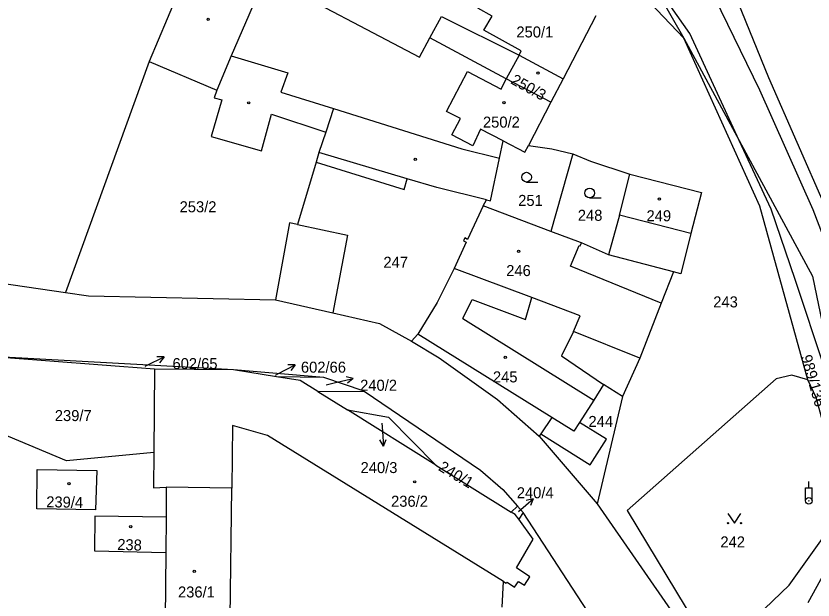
# Model space of a CAD drawing. Extents: x -757266 to -753360, y -1162585 to -1157740.
# Drawn here: x -755076.1 to -754953.1, y -1161480 to -1161389.8 of the extents above; entities that cross this region are included whole.
import ezdxf

# ---------------------------------------------------------------- set-up
doc = ezdxf.new("R2010")
doc.units = 0
for name, color, linetype in [('Hranice parcel', 7, 'Continuous'), ('Parcelní čísla', 7, 'Continuous'), ('Pop  PČ popisy', 7, 'Continuous'), ('Poz předměty', 7, 'Continuous'), ('Vnitřní kresba', 7, 'Continuous'), ('Značky budov', 7, 'Continuous'), ('Značky kultur', 7, 'Continuous')]:
    doc.layers.add(name, color=color, linetype=linetype)

msp = doc.modelspace()

# ---------------------------------------------------------------- linework, layer by layer
at = {"layer": 'Hranice parcel'}
for p, q in [((-755048.2, -1161379.47), (-755055.56, -1161396.89)), ((-754979.4, -1161382.11), (-754973.01, -1161393.26)), ((-754986.59, -1161389.82), (-754991.63, -1161399.56)), ((-755055.56, -1161396.89), (-755068.43, -1161432.57)), ((-754991.63, -1161399.56), (-754993.55, -1161403.18)), ((-754993.55, -1161403.18), (-754997, -1161409.84)), ((-754990.14, -1161411.15), (-754993.55, -1161423.12)), ((-754982.98, -1161420.63), (-754981.34, -1161414.29)), ((-755004.02, -1161419.18), (-755003.49, -1161418.25)), ((-754993.55, -1161423.12), (-755004.02, -1161419.18)), ((-754971.94, -1161423.45), (-754982.98, -1161420.63)), ((-755042.52, -1161444.48), (-755081.11, -1161442.37)), ((-755054.7, -1161444.4), (-755081.11, -1161442.37)), ((-754979.84, -1161442.68), (-754982.48, -1161448.61)), ((-755054.7, -1161444.4), (-755054.84, -1161457.25)), ((-755042.52, -1161444.48), (-755054.7, -1161444.4)), ((-755028.6, -1161445.65), (-755042.52, -1161444.48)), ((-755035.91, -1161445.56), (-755042.52, -1161444.48)), ((-755028.6, -1161445.65), (-755035.91, -1161445.56)), ((-755022.34, -1161447.76), (-755028.6, -1161445.65)), ((-755029.52, -1161447.84), (-755022.34, -1161447.76)), ((-755029.52, -1161447.84), (-755024.95, -1161450.69)), ((-754982.48, -1161448.61), (-754986.4, -1161465.19)), ((-755011.3, -1161459.19), (-755024.95, -1161450.69)), ((-754995.37, -1161454.74), (-754986.4, -1161465.19)), ((-755011.3, -1161459.19), (-754999.67, -1161466.44)), ((-755052.93, -1161462.61), (-755052.94, -1161467.24)), ((-754998.72, -1161465.52), (-754999.67, -1161466.44)), ((-754997.85, -1161466.5), (-754998.72, -1161465.52)), ((-754986.4, -1161465.19), (-754969.21, -1161489.94)), ((-755052.94, -1161467.24), (-755052.95, -1161472.69)), ((-754997.85, -1161466.5), (-754998.51, -1161467.56)), ((-754978.62, -1161495.89), (-754997.85, -1161466.5)), ((-755052.95, -1161472.69), (-755053.17, -1161489.72)), ((-755001.04, -1161481.14), (-755000.88, -1161477.19))]:
    msp.add_line(p, q, dxfattribs=at)
for points in [[(-754973.01, -1161393.26), (-754992.87, -1161372.36), (-755014.97, -1161353.78), (-755031.64, -1161333.48)], [(-755013.14, -1161343.79), (-754982.7, -1161367.02), (-754964.72, -1161387.71), (-754959.99, -1161399.35), (-754951.21, -1161419.33), (-754946.51, -1161428.67)], [(-755048.2, -1161379.47), (-755037.56, -1161383.7), (-755013.83, -1161396.2), (-755012.21, -1161393.22)], [(-755012.21, -1161393.22), (-755010.42, -1161389.94), (-754998.45, -1161395.88), (-754991.63, -1161399.56)], [(-754993.55, -1161403.18), (-755000.43, -1161399.58), (-755012.21, -1161393.22)], [(-754953.91, -1161446.03), (-754961.29, -1161419.21), (-754973.01, -1161393.26)], [(-754973.01, -1161393.26), (-754964.47, -1161409.1), (-754953.18, -1161430.02), (-754949.55, -1161447.4), (-754946.29, -1161464.12)], [(-755191.52, -1161394.71), (-755190.39, -1161394.84), (-755136.4, -1161414.19), (-755092.74, -1161429.01), (-755068.43, -1161432.57)], [(-755055.56, -1161396.89), (-755045.08, -1161401.31), (-755045.52, -1161402.47), (-755044.33, -1161402.81), (-755045.95, -1161408.44), (-755038.18, -1161410.68), (-755036.65, -1161405.03), (-755028.27, -1161407.81), (-755029.34, -1161410.94)], [(-755003.49, -1161418.25), (-755002.86, -1161418.4), (-755001.48, -1161411.8), (-755000.92, -1161409.13), (-754997.56, -1161410.87), (-754997, -1161409.84)], [(-754997, -1161409.84), (-754993.42, -1161410.38), (-754990.14, -1161411.15)], [(-755029.34, -1161410.94), (-755029.78, -1161412.42), (-755032.63, -1161422.04), (-755033.86, -1161421.77), (-755036.04, -1161433.7)], [(-755003.49, -1161418.25), (-755011.15, -1161416.35), (-755015.73, -1161414.99), (-755029.34, -1161410.94)], [(-754990.14, -1161411.15), (-754987.45, -1161412.29), (-754981.34, -1161414.29)], [(-754981.34, -1161414.29), (-754970.29, -1161417.11), (-754971.94, -1161423.45)], [(-755004.02, -1161419.18), (-755006.39, -1161424.34), (-755006.84, -1161424.13), (-755007.05, -1161424.57), (-755006.6, -1161424.78), (-755008.46, -1161428.84)], [(-754982.98, -1161420.63), (-754984.68, -1161426.71), (-754988.81, -1161424.9), (-754989, -1161424.83), (-754993.55, -1161423.12)], [(-754971.94, -1161423.45), (-754973.49, -1161429.65), (-754974.61, -1161429.35), (-754976.53, -1161434.21), (-754979.84, -1161442.68)], [(-755008.46, -1161428.84), (-755011.08, -1161434.1), (-755014.1, -1161438.97), (-755015.04, -1161440.07)], [(-754979.84, -1161442.68), (-754990.07, -1161438.58), (-754989.02, -1161436.13), (-754996.47, -1161433.34), (-755008.46, -1161428.84)], [(-755068.43, -1161432.57), (-755064.89, -1161433.06), (-755036.04, -1161433.7)], [(-755036.04, -1161433.7), (-755027.2, -1161435.69), (-755020.01, -1161437.34), (-755015.04, -1161440.07)], [(-755015.04, -1161440.07), (-755010.8, -1161442.63), (-755001.79, -1161449.07), (-754995.37, -1161454.74)], [(-755029.52, -1161447.84), (-755032.24, -1161446.16), (-755035.91, -1161445.56)], [(-754953.91, -1161446.03), (-754956.35, -1161445.32), (-754958.79, -1161445.88), (-754981.78, -1161466.23), (-754968.18, -1161488.69)], [(-754951.1, -1161469.8), (-754949.73, -1161466.39), (-754949.35, -1161463.05), (-754949.71, -1161459.34), (-754952.59, -1161448.77), (-754953.91, -1161446.03)], [(-754982.48, -1161448.61), (-754985.43, -1161446.75), (-754986.91, -1161449.16), (-754989.15, -1161452.64), (-754990, -1161453.97), (-754993.42, -1161451.84), (-754995.09, -1161454.35), (-754995.37, -1161454.74)], [(-755022.34, -1161447.76), (-755004.4, -1161459.96), (-755000.98, -1161462.96), (-754998.72, -1161465.52)], [(-755024.95, -1161450.69), (-755018.59, -1161451.8), (-755011.3, -1161459.19)], [(-755054.84, -1161457.25), (-755068.32, -1161458.53), (-755084.64, -1161451.67)], [(-755000.88, -1161477.19), (-755037.27, -1161454.63), (-755040.14, -1161453.82), (-755042.68, -1161453.1), (-755042.78, -1161462.74), (-755052.93, -1161462.61)], [(-755054.84, -1161457.25), (-755054.89, -1161462.7), (-755052.93, -1161462.61)], [(-755072.86, -1161465.97), (-755072.8, -1161459.87), (-755063.61, -1161460.04), (-755063.8, -1161466.1), (-755072.86, -1161465.97)], [(-755052.94, -1161467.24), (-755063.93, -1161467.1), (-755064, -1161472.46), (-755052.95, -1161472.69)], [(-754998.51, -1161467.56), (-754999.04, -1161466.83), (-754999.67, -1161466.44)], [(-755000.88, -1161477.19), (-755000.46, -1161477.45), (-755000.31, -1161477.27), (-754999.14, -1161478.03), (-754998.57, -1161477.18), (-754997.64, -1161477.75), (-754996.81, -1161476.46), (-754998.87, -1161475.05), (-754996.29, -1161470.65), (-754998.51, -1161467.56)], [(-754968.18, -1161488.69), (-754956.77, -1161477.72), (-754951.1, -1161469.8)]]:
    msp.add_lwpolyline(points, dxfattribs=at)
at = {"layer": 'Pop  PČ popisy'}
for p, q in [((-755055.94, -1161443.81), (-755053.243, -1161442.494)), ((-755053.243, -1161442.494), (-755054.362, -1161442.483)), ((-755053.243, -1161442.494), (-755053.923, -1161443.384)), ((-755056.17, -1161443.93), (-755055.94, -1161443.81)), ((-755035.66, -1161445.1), (-755033.01, -1161443.691)), ((-755033.01, -1161443.691), (-755034.13, -1161443.719)), ((-755033.01, -1161443.691), (-755033.659, -1161444.603)), ((-755036.02, -1161445.3), (-755035.66, -1161445.1)), ((-755026.97, -1161446.52), (-755024.046, -1161445.845)), ((-755024.046, -1161445.845), (-755025.134, -1161445.582)), ((-755024.046, -1161445.845), (-755024.909, -1161446.558)), ((-755028.25, -1161446.82), (-755026.97, -1161446.52)), ((-755019.62, -1161452.74), (-755019.58, -1161453.29)), ((-755019.58, -1161453.29), (-755019.371, -1161456.284)), ((-755019.371, -1161456.284), (-755019.94, -1161455.32)), ((-755019.371, -1161456.284), (-755018.941, -1161455.25)), ((-754998.54, -1161466.35), (-754996.275, -1161464.381)), ((-754996.275, -1161464.381), (-754997.359, -1161464.66)), ((-754996.275, -1161464.381), (-754996.702, -1161465.416)), ((-754998.57, -1161466.38), (-754998.54, -1161466.35))]:
    msp.add_line(p, q, dxfattribs=at)
at = {"layer": 'Poz předměty'}
for p, q in [((-754953.75, -1161462.716), (-754953.75, -1161461.716)), ((-754954.25, -1161462.716), (-754953.25, -1161462.716)), ((-754954.25, -1161464.716), (-754954.25, -1161462.716)), ((-754953.25, -1161464.716), (-754953.25, -1161462.716))]:
    msp.add_line(p, q, dxfattribs=at)
for radius in [0.5, 0.0303]:
    msp.add_circle((-754953.75, -1161464.7176), radius, dxfattribs=at)
at = {"layer": 'Vnitřní kresba'}
for p, q in [((-754972.12, -1161392.56), (-754979.4, -1161382.11)), ((-755037.56, -1161383.7), (-755042.86, -1161395.99)), ((-754969.29, -1161384.92), (-754961.36, -1161401.24)), ((-755002.62, -1161389.87), (-755004.8, -1161388.66)), ((-755003.92, -1161392.06), (-755002.62, -1161389.87)), ((-754998.12, -1161395.22), (-755003.92, -1161392.06)), ((-754964.47, -1161409.1), (-754972.12, -1161392.56)), ((-754998.45, -1161395.88), (-755000.43, -1161399.58)), ((-754998.45, -1161395.88), (-754998.12, -1161395.22)), ((-755042.86, -1161395.99), (-755045.08, -1161401.31)), ((-755042.86, -1161395.99), (-755034.16, -1161398.63)), ((-755034.16, -1161398.63), (-755035.21, -1161401.6)), ((-755009.66, -1161404.61), (-755006.43, -1161398.44)), ((-755006.43, -1161398.44), (-755001.24, -1161401.15)), ((-755001.24, -1161401.15), (-755000.43, -1161399.58)), ((-755035.21, -1161401.6), (-755027.11, -1161404.15)), ((-754961.36, -1161401.24), (-754953.13, -1161419.71)), ((-755027.11, -1161404.15), (-755028.27, -1161407.81)), ((-755027.11, -1161404.15), (-755007.28, -1161410.36)), ((-755007.52, -1161405.66), (-755009.66, -1161404.61)), ((-755008.82, -1161408.22), (-755007.52, -1161405.66)), ((-755005.58, -1161409.89), (-755008.82, -1161408.22)), ((-755004.41, -1161407.32), (-755005.58, -1161409.89)), ((-755000.92, -1161409.13), (-755004.41, -1161407.32)), ((-754959.56, -1161419.7), (-754964.47, -1161409.1)), ((-755007.28, -1161410.36), (-755001.48, -1161411.8)), ((-755029.78, -1161412.42), (-755016.21, -1161416.65)), ((-755016.21, -1161416.65), (-755015.73, -1161414.99)), ((-754955.84, -1161430.53), (-754959.56, -1161419.7)), ((-754953.13, -1161419.71), (-754948.58, -1161431.71)), ((-755032.63, -1161422.04), (-755024.94, -1161423.72)), ((-755024.94, -1161423.72), (-755027.2, -1161435.69)), ((-754990.54, -1161428.48), (-754989.19, -1161425.27)), ((-754989.19, -1161425.27), (-754989.05, -1161425.32)), ((-754989.05, -1161425.32), (-754988.81, -1161424.9)), ((-754974.61, -1161429.35), (-754984.68, -1161426.71)), ((-754976.53, -1161434.21), (-754990.54, -1161428.48)), ((-754951.26, -1161444.31), (-754955.84, -1161430.53)), ((-755007.12, -1161436.57), (-755005.7, -1161433.65)), ((-755005.7, -1161433.65), (-754997.47, -1161436.71)), ((-754997.47, -1161436.71), (-754996.47, -1161433.34)), ((-755007.12, -1161436.57), (-754986.91, -1161449.16)), ((-754993.42, -1161451.84), (-755014.1, -1161438.97)), ((-754990.07, -1161438.58), (-754991.91, -1161442.35)), ((-754991.91, -1161442.35), (-754985.43, -1161446.75)), ((-754984.98, -1161455.21), (-754989.15, -1161452.64)), ((-754995.09, -1161454.35), (-754987.51, -1161459.14)), ((-754987.51, -1161459.14), (-754984.98, -1161455.21)), ((-755043.05, -1161482.71), (-755042.78, -1161462.74)), ((-754953.86, -1161480.41), (-754948.59, -1161470.84))]:
    msp.add_line(p, q, dxfattribs=at)
at = {"layer": 'Značky budov'}
for centre in [(-755046.4368, -1161390.3692), (-754995.5368, -1161398.6692), (-755040.1768, -1161403.2592), (-755000.7968, -1161403.2492), (-755014.4668, -1161411.9692), (-754976.8068, -1161418.1292), (-754998.5368, -1161426.1892), (-755000.5968, -1161442.5492), (-755067.9268, -1161462.0592), (-755014.5568, -1161461.7792), (-755058.3768, -1161468.7192), (-755048.5768, -1161475.5892)]:
    msp.add_circle(centre, 0.175, dxfattribs=at)
at = {"layer": 'Značky kultur'}
for p, q in [((-754997.303, -1161415.49), (-754995.553, -1161415.49)), ((-754987.563, -1161417.95), (-754985.813, -1161417.95))]:
    msp.add_line(p, q, dxfattribs=at)
msp.add_lwpolyline([(-754966.22, -1161466.659), (-754965.22, -1161468.16), (-754964.22, -1161466.659)], dxfattribs=at)
for centre, radius in [((-754997.3029, -1161414.7398), 0.75), ((-754987.5629, -1161417.1998), 0.75), ((-754966.22, -1161468.1595), 0.1), ((-754964.22, -1161468.1595), 0.1)]:
    msp.add_circle(centre, radius, dxfattribs=at)

# ---------------------------------------------------------------- texts
at = {"layer": 'Parcelní čísla'}
for s, p in [('250/1', (-754998.87, -1161393.17)), ('250/2', (-755004.03, -1161407.09)), ('251', (-754998.59, -1161419.18)), ('253/2', (-755050.84, -1161420.16)), ('248', (-754989.39, -1161421.48)), ('249', (-754978.79, -1161421.55)), ('247', (-755019.39, -1161428.73)), ('246', (-755000.44, -1161430.01)), ('243', (-754968.49, -1161434.85)), ('602/65', (-755051.94, -1161444.378)), ('602/66', (-755032.12, -1161444.928)), ('245', (-755002.49, -1161446.43)), ('240/2', (-755022.98, -1161447.718)), ('239/7', (-755070.1, -1161452.4)), ('244', (-754987.75, -1161453.31)), ('240/3', (-755022.917, -1161460.428)), ('240/4', (-754998.81, -1161464.32)), ('236/2', (-755018.21, -1161465.63)), ('242', (-754967.39, -1161471.91)), ('236/1', (-755051.09, -1161479.64))]:
    msp.add_text(s, height=1.7, dxfattribs=at).set_placement(p)
for s, rotation, p in [('250/3', 331, (-754999.872, -1161400.213)), ('989/136', 286, (-754954.987, -1161442.444)), ('240/1', 329, (-755011.037, -1161459.918)), ('239/4', 359, (-755071.434, -1161465.709)), ('238', 358, (-755060.489, -1161472.279))]:
    msp.add_text(s, height=1.7, rotation=rotation, dxfattribs=at).set_placement(p)

doc.saveas('drawing.dxf')
